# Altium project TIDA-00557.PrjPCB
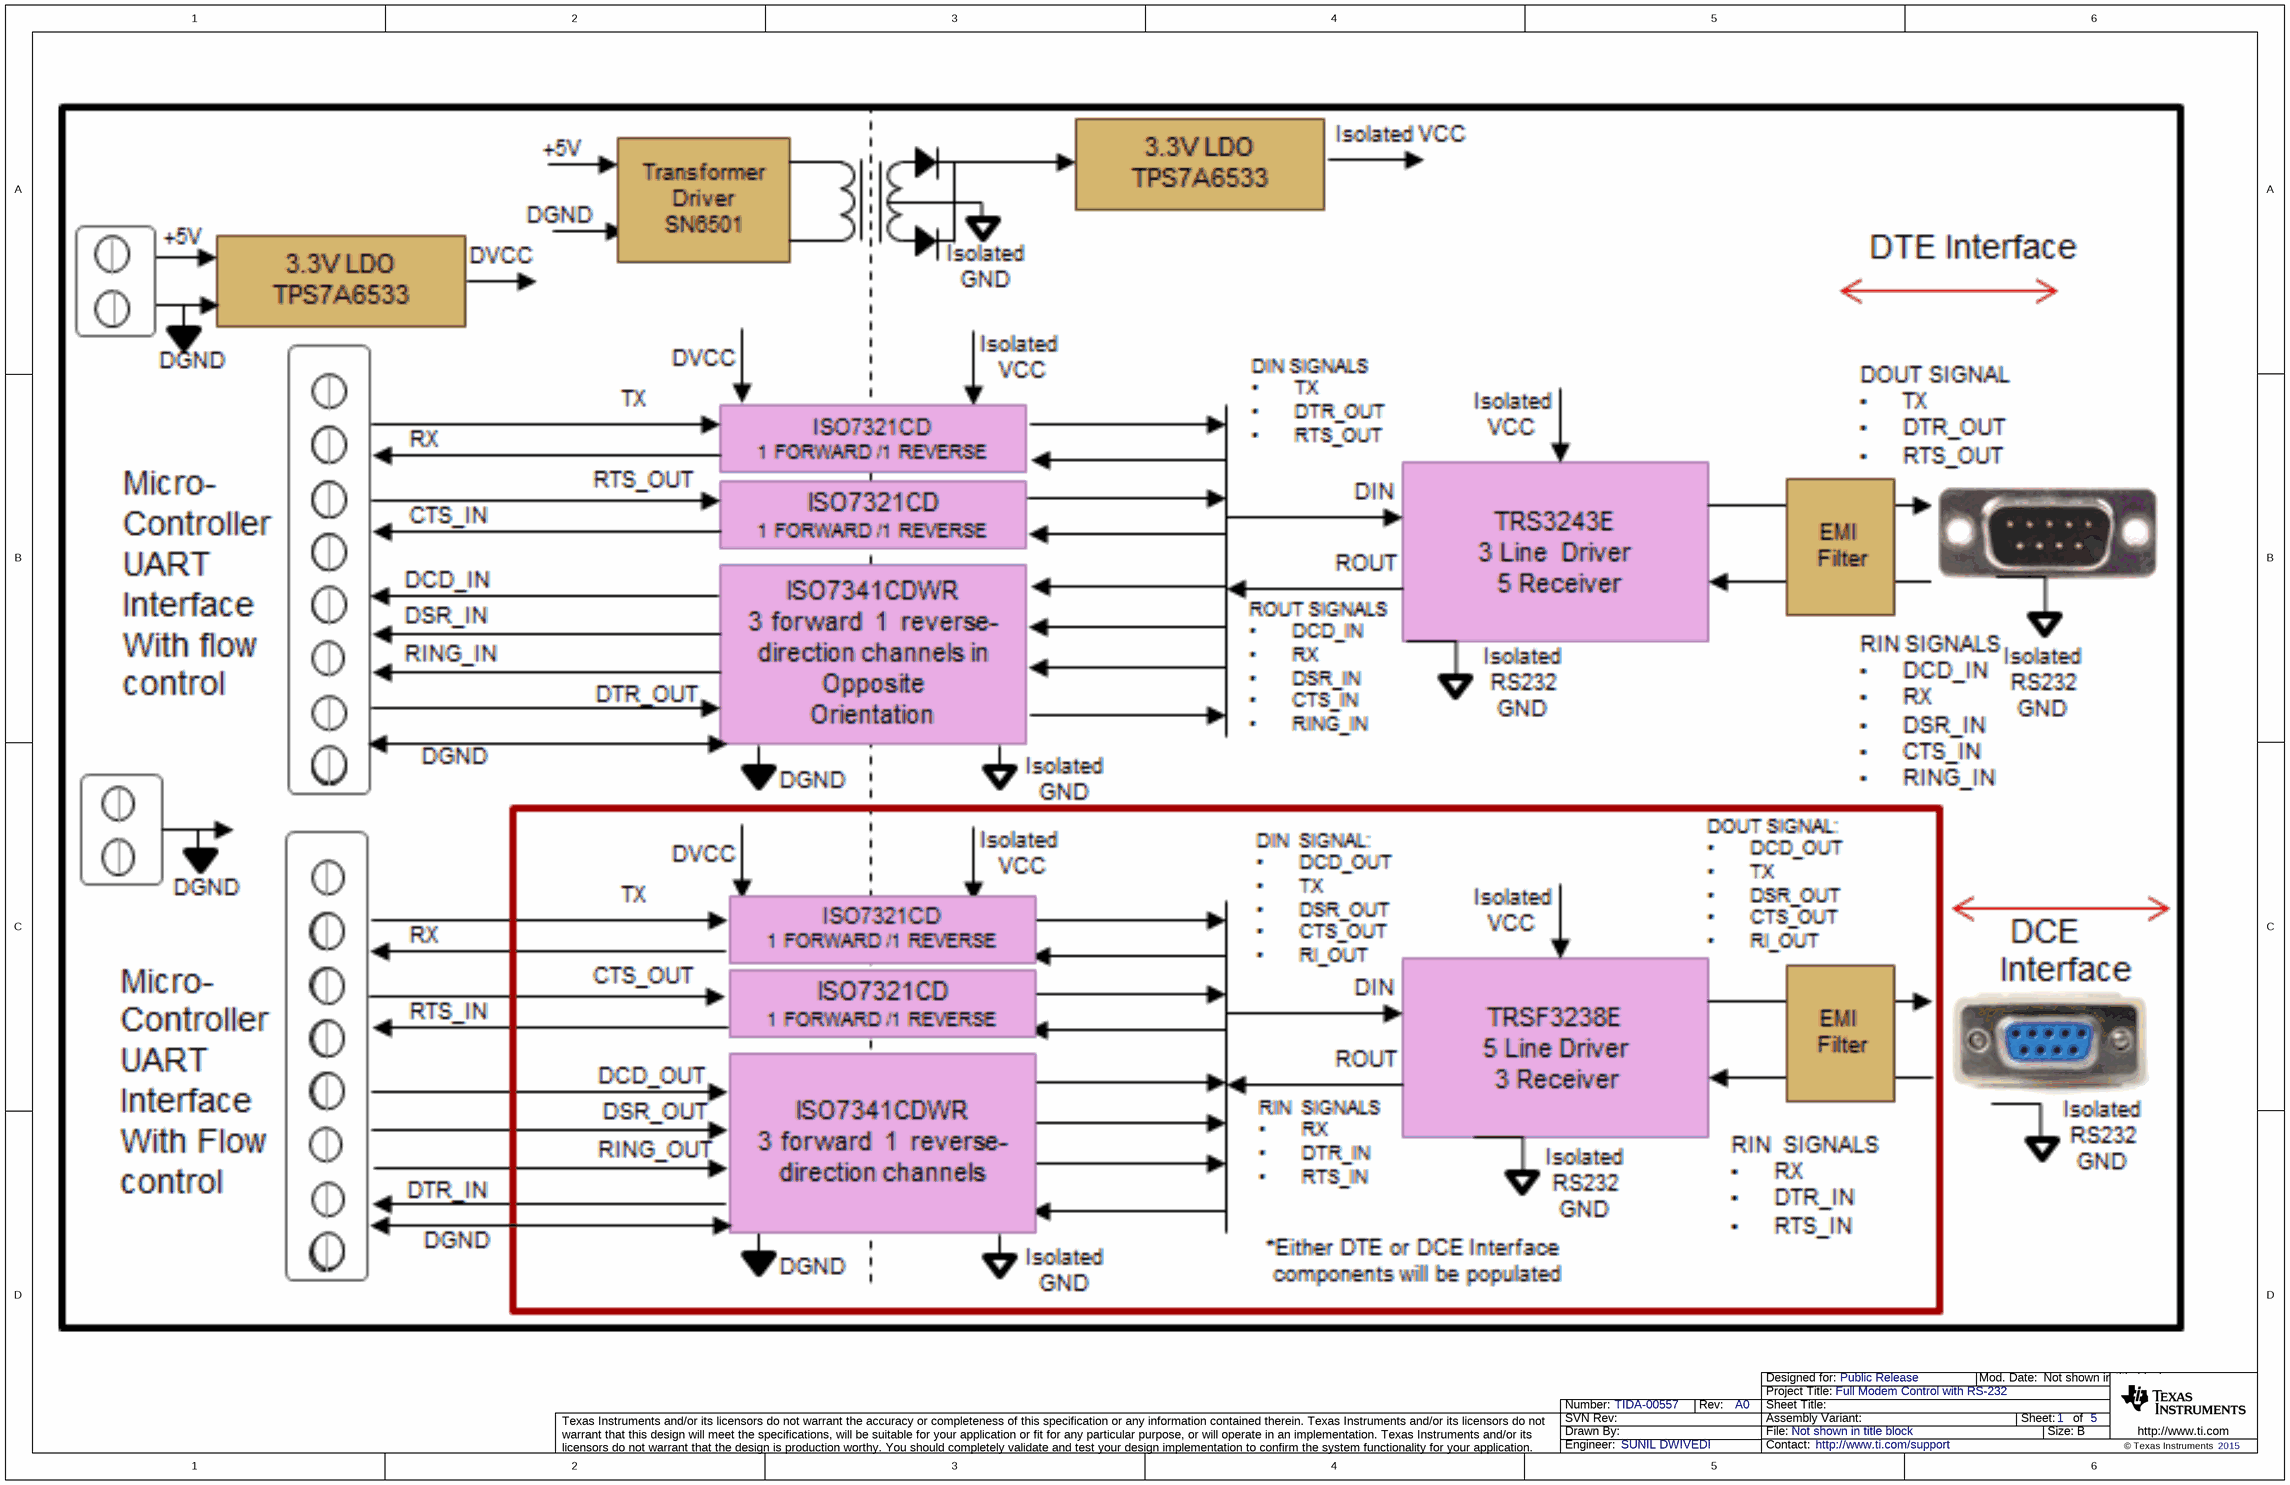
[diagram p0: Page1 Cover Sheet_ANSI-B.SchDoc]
CopyrightYear: 2015; PCB_Layout: AVINASH N; PCB_Rev: E2; PRJ_Customer: Public Release; PRJ_Engineer: SUNIL DWIVEDI; PRJ_Number: TIDA-00557; PRJ_Title: Full Modem Control with RS-232; SCH_Rev: A0; TechSupport: http://www.ti.com/support
5 sheets, 146 parts. Net scope: global (net labels, ports and power ports of the same name join across sheets).
Board file: TIDA-00557.PcbDoc
Sheets:
  Page1 Cover Sheet_ANSI-B.SchDoc
  Page2 DTE-DCE.SchDoc
  Page3 DCE-DTE.SchDoc
  Page4 Power Supply.SchDoc
  Page5 Hardware_ANSI-B.SchDoc

## Sheet Page1 Cover Sheet_ANSI-B.SchDoc
size 431 x 279 mm; Date: Not shown in title block; ApprovedBy: Not shown in title block; CheckedBy: Not shown in title block; Author: Not shown in title block; CompanyName: Not shown in title block; Engineer: Not shown in title block; Organization: Not shown in title block; Address1: Not shown in title block; Address2: Not shown in title block; Address3: Not shown in title block; Address4: Not shown in title block; DocumentNumber: 1; Revision: Use project parameter SCH_Rev; SheetNumber: 1; SheetTotal: 5; PageSetup: Record=PageOptions¦CenterHorizontal=True¦CenterVertical=True¦PrintScale=1.00¦XCorrection=1.00¦YCorrection=1.00¦PrintKind=0¦BorderSize=5000000¦LeftOffset=0¦BottomOffset=0¦Orientation=2¦PaperLength=1000¦PaperWidth=1000¦Scale=100¦PaperSource=15¦PrintQuality=600¦MediaType=1¦DitherType=10¦PaperKind=Letter¦PrintScaleMode=1

## Sheet Page2 DTE-DCE.SchDoc
size 431 x 279 mm; Date: Not shown in title block; ApprovedBy: Not shown in title block; CheckedBy: Not shown in title block; Author: Not shown in title block; CompanyName: Not shown in title block; Engineer: Not shown in title block; Organization: Not shown in title block; Address1: Not shown in title block; Address2: Not shown in title block; Address3: Not shown in title block; Address4: Not shown in title block; DocumentNumber: 1; Revision: Use project parameter SCH_Rev; SheetNumber: 2; SheetTotal: 5; PageSetup: Record=PageOptions¦CenterHorizontal=True¦CenterVertical=True¦PrintScale=1.00¦XCorrection=1.00¦YCorrection=1.00¦PrintKind=0¦BorderSize=5000000¦LeftOffset=0¦BottomOffset=0¦Orientation=2¦PaperLength=1000¦PaperWidth=1000¦Scale=100¦PaperSource=15¦PrintQuality=600¦MediaType=1¦DitherType=10¦PaperKind=Letter¦PrintScaleMode=1
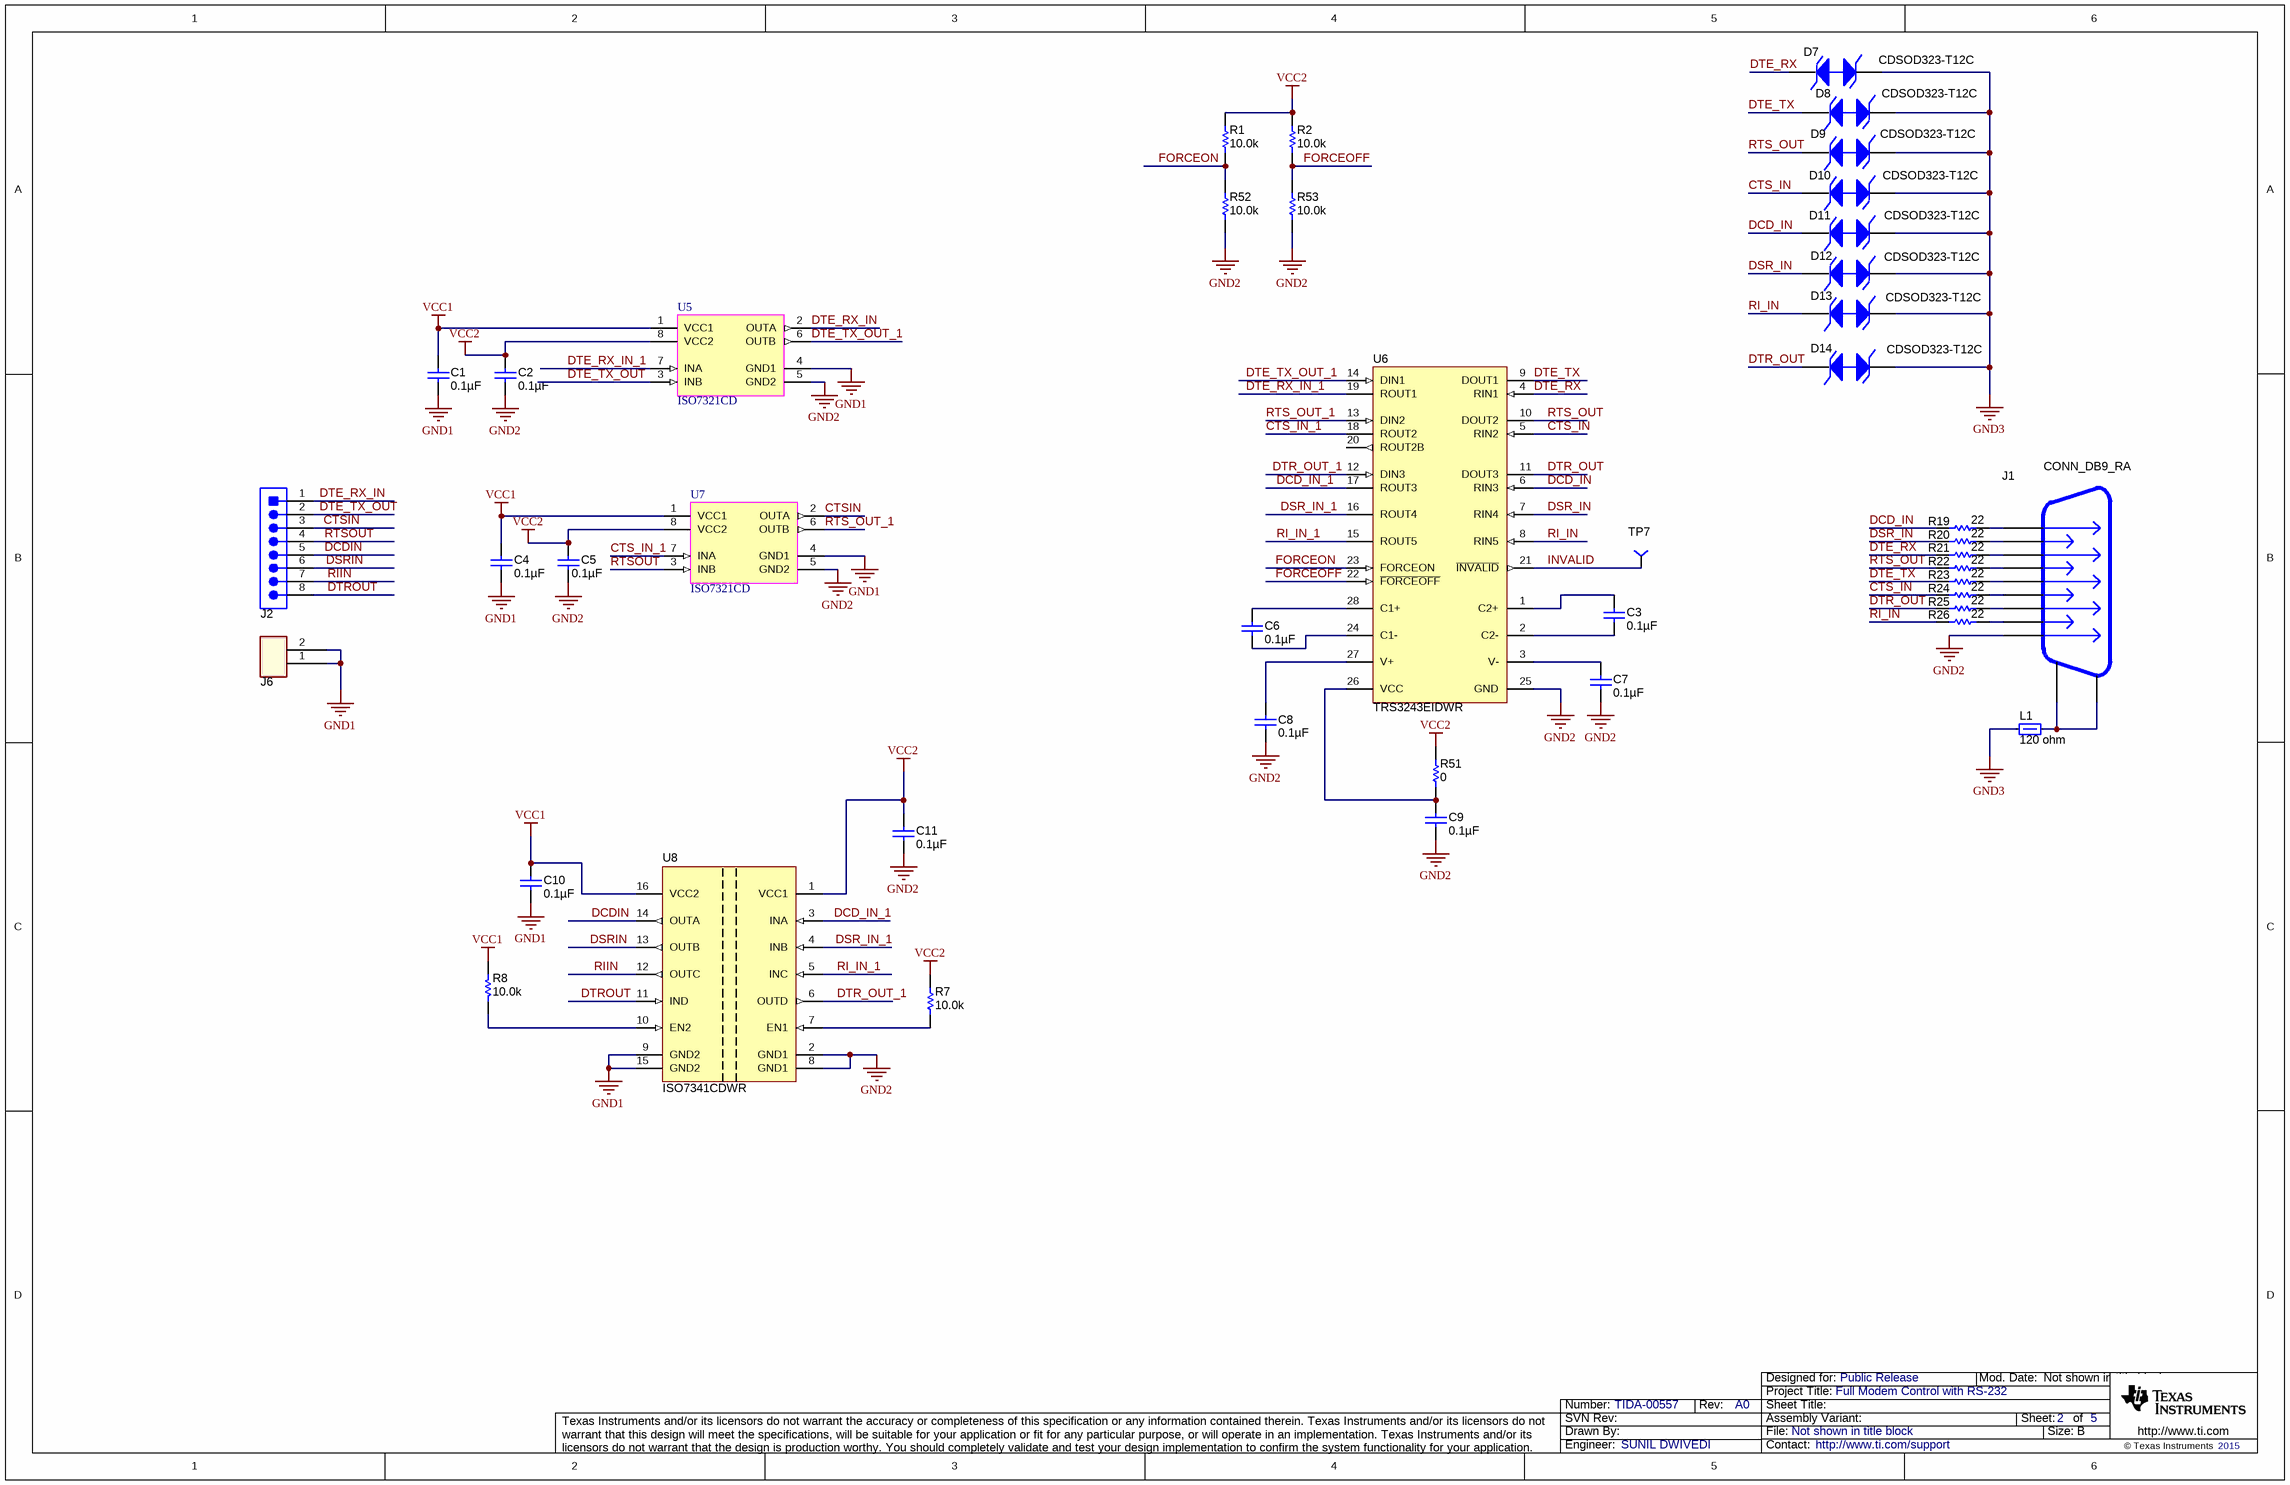
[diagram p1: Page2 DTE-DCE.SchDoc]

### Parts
C1  ValueDisplayed: 0.1µF  [0603]  (hidden comment: C0603C104K5RACTU)
C2  ValueDisplayed: 0.1µF  [0603]  (hidden comment: C0603C104K5RACTU)
C3  ValueDisplayed: 0.1µF  [0603]  (hidden comment: C0603C104K5RACTU)
C4  ValueDisplayed: 0.1µF  [0603]  (hidden comment: C0603C104K5RACTU)
C5  ValueDisplayed: 0.1µF  [0603]  (hidden comment: C0603C104K5RACTU)
C6  ValueDisplayed: 0.1µF  [0603]  (hidden comment: C0603C104K5RACTU)
C7  ValueDisplayed: 0.1µF  [0603]  (hidden comment: C0603C104K5RACTU)
C8  ValueDisplayed: 0.1µF  [0603]  (hidden comment: C0603C104K5RACTU)
C9  ValueDisplayed: 0.1µF  [0603]  (hidden comment: C0603C104K5RACTU)
C10  ValueDisplayed: 0.1µF  [0603]  (hidden comment: C0603C104K5RACTU)
C11  ValueDisplayed: 0.1µF  [0603]  (hidden comment: C0603C104K5RACTU)
D7  CDSOD323-T12C  [sod-323]
D8  CDSOD323-T12C  [sod-323]
D9  CDSOD323-T12C  [sod-323]
D10  CDSOD323-T12C  [sod-323]
D11  CDSOD323-T12C  [sod-323]
D12  CDSOD323-T12C  [sod-323]
D13  CDSOD323-T12C  [sod-323]
D14  CDSOD323-T12C  [sod-323]
J1  CONN_DB9_RA  [DB9_RA]
J2  1725711  [CONN_1725711]  (value not drawn)
J6  CON-OSTVN02A150  [CN2_MTB_P100_PD80_D1.1_S5.54X6.5_STACK]  (value not drawn)
L1  value 120 ohm  [0805_HV]  (hidden comment: BLM21AG121SN1D)
R1  value 10.0k  [0603]  (hidden comment: CRCW060310K0FKEA)
R2  value 10.0k  [0603]  (hidden comment: CRCW060310K0FKEA)
R7  value 10.0k  [0603]  (hidden comment: CRCW060310K0FKEA)
R8  value 10.0k  [0603]  (hidden comment: CRCW060310K0FKEA)
R19  ValueDisplayed: 22  [2512]  (hidden comment: RPC2512JT22R0)
R20  ValueDisplayed: 22  [2512]  (hidden comment: RPC2512JT22R0)
R21  ValueDisplayed: 22  [2512]  (hidden comment: RPC2512JT22R0)
R22  ValueDisplayed: 22  [2512]  (hidden comment: RPC2512JT22R0)
R23  ValueDisplayed: 22  [2512]  (hidden comment: RPC2512JT22R0)
R24  ValueDisplayed: 22  [2512]  (hidden comment: RPC2512JT22R0)
R25  ValueDisplayed: 22  [2512]  (hidden comment: RPC2512JT22R0)
R26  ValueDisplayed: 22  [2512]  (hidden comment: RPC2512JT22R0)
R51  ValueDisplayed: 0  [0603]  (hidden comment: CRCW06030000Z0EA)
R52  value 10.0k  [0603]  (hidden comment: CRCW060310K0FKEA)
R53  value 10.0k  [0603]  (hidden comment: CRCW060310K0FKEA)
TP7  TP-040_RND  [TP-040_RND]  (value not drawn)
U5  ISO7321CD
U6  TRS3243EIDWR  [DW0028A_N]
U7  ISO7321CD
U8  ISO7341CDWR  [DW0016B_HV]

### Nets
GND1: C1.2 C4.2 C10.2 J6.1 J6.2 U5.4(GND1) U7.4(GND1) U8.9(GND2) U8.15(GND2)
GND2: C2.2 C5.2 C7.2 C8.2 C9.2 C11.2 J1.5 R52.2 R53.1 U5.5(GND2) U6.25(GND) U7.5(GND2) U8.2(GND1) U8.8(GND1)
GND3: D7.2 D8.2 D9.2 D10.2 D11.2 D12.2 D13.2 D14.2 L1.2
VCC1: C1.1 C4.1 C10.1 R8.2 U5.1(VCC1) U7.1(VCC1) U8.16(VCC2)
VCC2: C2.1 C5.1 C11.1 R1.2 R2.2 R7.2 R51.1 U5.8(VCC2) U7.8(VCC2) U8.1(VCC1)
CTS_IN: D10.1 R24.1 U6.5(RIN2)
CTS_IN_1: U6.18(ROUT2) U7.7(INA)
CTSIN: J2.3 U7.2(OUTA)
DCD_IN: D11.1 R19.1 U6.6(RIN3)
DCD_IN_1: U6.17(ROUT3) U8.3(INA)
DCDIN: J2.5 U8.14(OUTA)
DSR_IN: D12.1 R20.1 U6.7(RIN4)
DSR_IN_1: U6.16(ROUT4) U8.4(INB)
DSRIN: J2.6 U8.13(OUTB)
DTE_RX: D7.1 R21.1 U6.4(RIN1)
DTE_RX_IN: J2.1 U5.2(OUTA)
DTE_RX_IN_1: U5.7(INA) U6.19(ROUT1)
DTE_TX: D8.1 R23.1 U6.9(DOUT1)
DTE_TX_OUT: J2.2 U5.3(INB)
DTE_TX_OUT_1: U5.6(OUTB) U6.14(DIN1)
DTR_OUT: D14.1 R25.1 U6.11(DOUT3)
DTR_OUT_1: U6.12(DIN3) U8.6(OUTD)
DTROUT: J2.8 U8.11(IND)
FORCEOFF: R2.1 R53.2 U6.22(~{FORCEOFF})
FORCEON: R1.1 R52.1 U6.23(FORCEON)
INVALID: TP7.1 U6.21(~{INVALID})
RI_IN: D13.1 R26.1 U6.8(RIN5)
RI_IN_1: U6.15(ROUT5) U8.5(INC)
RIIN: J2.7 U8.12(OUTC)
RTS_OUT: D9.1 R22.1 U6.10(DOUT2)
RTS_OUT_1: U6.13(DIN2) U7.6(OUTB)
RTSOUT: J2.4 U7.3(INB)
NetC3_1: C3.1 U6.1(C2+)
NetC3_2: C3.2 U6.2(C2-)
NetC6_1: C6.1 U6.28(C1+)
NetC6_2: C6.2 U6.24(C1-)
NetC7_1: C7.1 U6.3(V-)
NetC8_1: C8.1 U6.27(V+)
NetC9_1: C9.1 R51.2 U6.26(VCC)
NetJ1_1: J1.1 R19.2
NetJ1_2: J1.2 R21.2
NetJ1_3: J1.3 R23.2
NetJ1_4: J1.4 R25.2
NetJ1_6: J1.6 R20.2
NetJ1_7: J1.7 R22.2
NetJ1_8: J1.8 R24.2
NetJ1_9: J1.9 R26.2
NetJ1_10: J1.10(MOUNT1) J1.11(MOUNT2) L1.1
NetR7_1: R7.1 U8.7(EN1)
NetR8_1: R8.1 U8.10(EN2)

Not connected (* = marked no-connect by the designer): U6 20(ROUT2B)

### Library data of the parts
C1-C11 = C0603C104K5RACTU: CAP, CERM, 0.1uF, 50V, +/-10%, X7R, 0603; Manufacturer: Kemet; Polarized: N; CompType: Capacitor; U/M: EA; Cap_F: 0.0000001; Tolerance_%: 10; Value1: Unknown; VDC_V: 50; TaMin_C: -55; TaMax_C: 125
D7-D14 = CDSOD323-T15SC: Diode, TVS, ARRAY, 19V, SOD323; Manufacturer: Bourns Inc.; Value: 19
J1 = CONN_DB9_RA: Connector, 9-pin D, Right Angle, Male; Manufacturer: AMP; PartNumber: 747250-4; area: 1.021 inch; Value: 747250-4
J2 = 1725711: Terminal Block, 8x1, 2.54 mm, TH; Manufacturer: Phoenix Contact; SymbolCreator: a0411947; U/M: EA
J6 = CON-OSTVN02A150: CONN TERM BLOCK 2.54MM 2POS PCB; Manufacturer: On Shore Technology Inc; SymbolCreator: x0120606; CompType: Terminal Block
L1 = BLM21AG121SN1D: Ferrite Bead, 120 ohm @ 100 MHz, 0.8 A, 0805; Manufacturer: MuRata; Imax_A: 0.8; DCR_ohm: 0.1; Value1: 0.1 ohm; Value2: 0.8A; ZTyp@100MHz_Ohm: 120
R1 R2 R7 R8 R52 R53 = CRCW060310K0FKEA: RES, 10.0k ohm, 1%, 0.1W, 0603; Manufacturer: Vishay-Dale; CompType: Resistor; Res_ohm: 10000; Value_Code: 10k0; Tolerance_%: 1; Power_W: 0.1; VDC_V: 75; TempCo: 100 ppm/C; EIA_Code: E96; U/M: EA
R19-R26 = CRCW251210R0FKEG: RES SMD 22 OHM 5% 1.5W 2512; Manufacturer: Vishay-Dale; CompType: Resistor; Value: 10.0; Res_ohm: 10; Value_Code: 10R0; Tolerance_%: 1; Value1: 1%; Value2: 1W; VDC_V: 500; TempCo: 100 ppm/C; EIA_Code: E96; U/M: EA
R51 = CRCW06030000Z0EA: RES, 0, 5%, 0.1 W, 0603; Manufacturer: Vishay-Dale; CompType: Resistor; Value: 0; Value_Code: 0000; Tolerance_%: 5; Power_W: 0.1; Value2: 0.1W; VDC_V: 75; TempCo: 200 ppm/C; EIA_Code: E24; U/M: EA
TP7 = TP-040_RND: Test Point, O.040 Hole; Manufacturer: STD; Value: STD
U5 U7 = ISO7321CD: IC, ISOLATOR DGTL 2CH 1/1, SOIC-8, ROHS; Manufacturer: TEXAS INSTRUMENTS; CompType: ISOLATOR IC; SymbolCreator: x0199378
U6 = TRS3243EIDWR: 3-V to 5.5-V Multichannel RS-232 Line Driver / Receiver with ±15-kV IEC ESD Protection, -40 to 85 degC, 28-Pin SOIC (DW), Green (RoHS & no Sb/Br); Manufacturer: Texas Instruments; Alternate Manufacturer: None; Alternate PartNumber: Equivalent; Drivers Per Package: 3; Receivers Per Package: 5; Supply Voltage(s)(V): 3.3 or 5.0; ESD HBM(kV): +/-15; ICC(Max)(mA): 1; Single Supply: TRUE
U8 = ISO7341CDWR: Robust EMC, Low Power, Quad-Channel Digital Isolators, DW0016B; Manufacturer: Texas Instruments; SymbolCreator: Altium; CompType: IC; U/M: EA

## Sheet Page3 DCE-DTE.SchDoc
size 431 x 279 mm; Date: Not shown in title block; ApprovedBy: Not shown in title block; CheckedBy: Not shown in title block; Author: Not shown in title block; CompanyName: Not shown in title block; Engineer: Not shown in title block; Organization: Not shown in title block; Address1: Not shown in title block; Address2: Not shown in title block; Address3: Not shown in title block; Address4: Not shown in title block; DocumentNumber: 1; Revision: Use project parameter SCH_Rev; SheetNumber: 3; SheetTotal: 5; PageSetup: Record=PageOptions|CenterHorizontal=True|CenterVertical=True|PrintScale=1.00|XCorrection=1.00|YCorrection=1.00|PrintKind=0|BorderSize=5000000|LeftOffset=0|BottomOffset=0|Orientation=2|PaperLength=1000|PaperWidth=1000|Scale=100|PaperSource=15|PrintQuality=600|MediaType=1|DitherType=10|PaperKind=Letter|PrintScaleMode=1
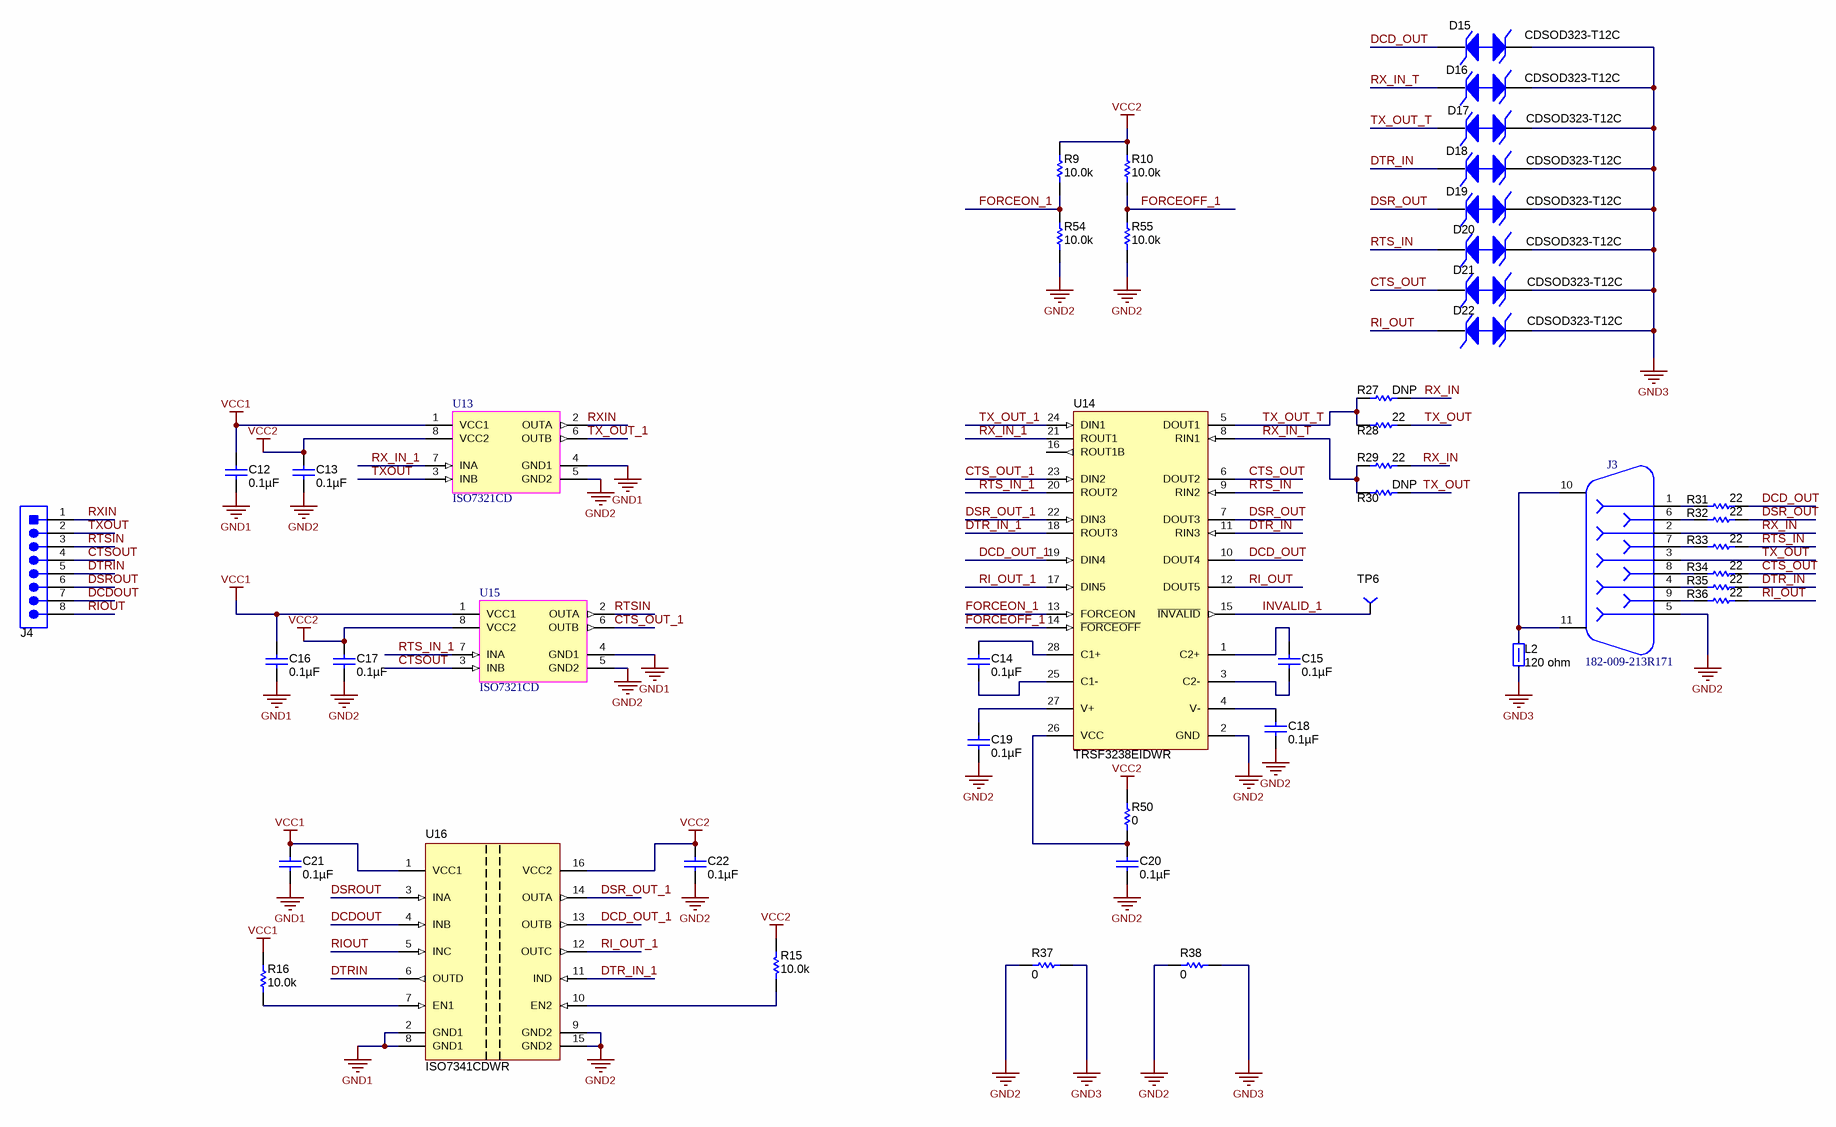
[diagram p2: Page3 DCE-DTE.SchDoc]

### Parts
C12  ValueDisplayed: 0.1µF  [0603]  (hidden comment: C0603C104K5RACTU)
C13  ValueDisplayed: 0.1µF  [0603]  (hidden comment: C0603C104K5RACTU)
C14  ValueDisplayed: 0.1µF  [0603]  (hidden comment: C0603C104K5RACTU)
C15  ValueDisplayed: 0.1µF  [0603]  (hidden comment: C0603C104K5RACTU)
C16  ValueDisplayed: 0.1µF  [0603]  (hidden comment: C0603C104K5RACTU)
C17  ValueDisplayed: 0.1µF  [0603]  (hidden comment: C0603C104K5RACTU)
C18  ValueDisplayed: 0.1µF  [0603]  (hidden comment: C0603C104K5RACTU)
C19  ValueDisplayed: 0.1µF  [0603]  (hidden comment: C0603C104K5RACTU)
C20  ValueDisplayed: 0.1µF  [0603]  (hidden comment: C0603C104K5RACTU)
C21  ValueDisplayed: 0.1µF  [0603]  (hidden comment: C0603C104K5RACTU)
C22  ValueDisplayed: 0.1µF  [0603]  (hidden comment: C0603C104K5RACTU)
D15  CDSOD323-T12C  [sod-323]
D16  CDSOD323-T12C  [sod-323]
D17  CDSOD323-T12C  [sod-323]
D18  CDSOD323-T12C  [sod-323]
D19  CDSOD323-T12C  [sod-323]
D20  CDSOD323-T12C  [sod-323]
D21  CDSOD323-T12C  [sod-323]
D22  CDSOD323-T12C  [sod-323]
J3  182-009-213R171  [NORCOMP_182-009-213R171]
J4  1725711  [CONN_1725711]  (value not drawn)
L2  value 120 ohm  [0805_HV]  (hidden comment: BLM21AG121SN1D)
R9  value 10.0k  [0603]  (hidden comment: CRCW060310K0FKEA)
R10  value 10.0k  [0603]  (hidden comment: CRCW060310K0FKEA)
R15  value 10.0k  [0603]  (hidden comment: CRCW060310K0FKEA)
R16  value 10.0k  [0603]  (hidden comment: CRCW060310K0FKEA)
R27  DNP  [2512]
R28  ValueDisplayed: 22  [2512]  (hidden comment: RPC2512JT22R0)
R29  ValueDisplayed: 22  [2512]  (hidden comment: RPC2512JT22R0)
R30  DNP  [2512]
R31  ValueDisplayed: 22  [2512]  (hidden comment: RPC2512JT22R0)
R32  ValueDisplayed: 22  [2512]  (hidden comment: RPC2512JT22R0)
R33  ValueDisplayed: 22  [2512]  (hidden comment: RPC2512JT22R0)
R34  ValueDisplayed: 22  [2512]  (hidden comment: RPC2512JT22R0)
R35  ValueDisplayed: 22  [2512]  (hidden comment: RPC2512JT22R0)
R36  ValueDisplayed: 22  [2512]  (hidden comment: RPC2512JT22R0)
R37  ValueDisplayed: 0  [0805_HV]  (hidden comment: CRCW08050000Z0EA)
R38  ValueDisplayed: 0  [0805_HV]  (hidden comment: CRCW08050000Z0EA)
R50  ValueDisplayed: 0  [0603]  (hidden comment: CRCW06030000Z0EA)
R54  value 10.0k  [0603]  (hidden comment: CRCW060310K0FKEA)
R55  value 10.0k  [0603]  (hidden comment: CRCW060310K0FKEA)
TP6  TP-040_RND  [TP-040_RND]  (value not drawn)
U13  ISO7321CD
U14  TRSF3238EIDWR  [DW0028A_N]
U15  ISO7321CD
U16  ISO7341CDWR  [DW0016B_HV]

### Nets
GND1: C12.2 C16.2 C21.2 U13.4(GND1) U15.4(GND1) U16.2(GND1) U16.8(GND1)
GND2: C13.2 C17.2 C18.2 C19.2 C20.2 C22.2 J3.5 R37.1 R38.1 R54.1 R55.1 U13.5(GND2) U14.2(GND) U15.5(GND2) U16.9(GND2) U16.15(GND2)
GND3: D15.2 D16.2 D17.2 D18.2 D19.2 D20.2 D21.2 D22.2 L2.2 R37.2 R38.2
VCC1: C12.1 C16.1 C21.1 R16.2 U13.1(VCC1) U15.1(VCC1) U16.1(VCC1)
VCC2: C13.1 C17.1 C22.1 R9.2 R10.2 R15.2 R50.2 U13.8(VCC2) U15.8(VCC2) U16.16(VCC2)
CTS_OUT: D21.1 R34.2 U14.6(DOUT2)
CTS_OUT_1: U14.23(DIN2) U15.6(OUTB)
CTSOUT: J4.4 U15.3(INB)
DCD_OUT: D15.1 R31.2 U14.10(DOUT4)
DCD_OUT_1: U14.19(DIN4) U16.13(OUTB)
DCDOUT: J4.7 U16.4(INB)
DSR_OUT: D19.1 R32.2 U14.7(DOUT3)
DSR_OUT_1: U14.22(DIN3) U16.14(OUTA)
DSROUT: J4.6 U16.3(INA)
DTR_IN: D18.1 R35.2 U14.11(RIN3)
DTR_IN_1: U14.18(ROUT3) U16.11(IND)
DTRIN: J4.5 U16.6(OUTD)
FORCEOFF_1: R10.1 R55.2 U14.14(~{FORCEOFF})
FORCEON_1: R9.1 R54.2 U14.13(FORCEON)
INVALID_1: TP6.1 U14.15(~{INVALID})
RI_OUT: D22.1 R36.2 U14.12(DOUT5)
RI_OUT_1: U14.17(DIN5) U16.12(OUTC)
RIOUT: J4.8 U16.5(INC)
RTS_IN: D20.1 R33.2 U14.9(RIN2)
RTS_IN_1: U14.20(ROUT2) U15.7(INA)
RTSIN: J4.3 U15.2(OUTA)
RX_IN: J3.2 R27.2 R29.2
RX_IN_1: U13.7(INA) U14.21(ROUT1)
RX_IN_T: D16.1 R29.1 R30.1 U14.8(RIN1)
RXIN: J4.1 U13.2(OUTA)
TX_OUT: J3.3 R28.2 R30.2
TX_OUT_1: U13.6(OUTB) U14.24(DIN1)
TX_OUT_T: D17.1 R27.1 R28.1 U14.5(DOUT1)
TXOUT: J4.2 U13.3(INB)
NetC14_1: C14.1 U14.28(C1+)
NetC14_2: C14.2 U14.25(C1-)
NetC15_1: C15.1 U14.1(C2+)
NetC15_2: C15.2 U14.3(C2-)
NetC18_1: C18.1 U14.4(V-)
NetC19_1: C19.1 U14.27(V+)
NetC20_1: C20.1 R50.1 U14.26(VCC)
NetJ3_1: J3.1 R31.1
NetJ3_4: J3.4 R35.1
NetJ3_6: J3.6 R32.1
NetJ3_7: J3.7 R33.1
NetJ3_8: J3.8 R34.1
NetJ3_9: J3.9 R36.1
NetJ3_10: J3.10 J3.11 L2.1
NetR15_1: R15.1 U16.10(EN2)
NetR16_1: R16.1 U16.7(EN1)

Not connected (* = marked no-connect by the designer): U14 16(ROUT1B)

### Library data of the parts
C12-C22 = C0603C104K5RACTU: as C1 on sheet Page2 DTE-DCE
D15-D22 = CDSOD323-T15SC: as D7 on sheet Page2 DTE-DCE
J3 = 182-009-213R171: CONN DB9 FEMALE R/A SOLDER TH; Manufacturer: NorComp; SymbolCreator: a0412235; CompType: Connector; U/M: EA
J4 = 1725711: as J2 on sheet Page2 DTE-DCE
L2 = BLM21AG121SN1D: as L1 on sheet Page2 DTE-DCE
R9 R10 R15 R16 R54 R55 = CRCW060310K0FKEA: as R1 on sheet Page2 DTE-DCE
R27 R30 = CRCW251210R0FKEG: Manufacturer: Vishay-Dale; CompType: Resistor; Value: 10.0; Res_ohm: 10; Value_Code: 10R0; Tolerance_%: 1; Value1: 1%; Value2: 1W; VDC_V: 500; TempCo: 100 ppm/C; EIA_Code: E96; U/M: EA
R28 R29 R31-R36 = CRCW251210R0FKEG: as R19 on sheet Page2 DTE-DCE
R37 R38 = CRCW08050000Z0EA: RES, 0, 5%, 0.125 W, 0805; Manufacturer: Vishay-Dale; CompType: Resistor; Value: 0; Value_Code: 0000; Tolerance_%: 5; Power_W: 0.125; Value2: 0.125W; VDC_V: 150; TempCo: 200 ppm/C; EIA_Code: E24; U/M: EA
R50 = CRCW06030000Z0EA: as R51 on sheet Page2 DTE-DCE
TP6 = TP-040_RND: as TP7 on sheet Page2 DTE-DCE
U13 U15 = ISO7321CD: as U5 on sheet Page2 DTE-DCE
U14 = TRSF3238EIDWR: 3-V to 5.5-V Multichannel RS-232 Line Driver / Receiver with ±15-kV ESD (HBM) Protection, -40 to 85 degC, 28-Pin SOIC (DW),  Green (RoHS & no Sb/Br); Manufacturer: Texas Instruments; Alternate Manufacturer: None; Alternate PartNumber: Equivalent; Drivers Per Package: 5; Receivers Per Package: 3; Supply Voltage(s)(V): 3.3 or 5.0; ESD HBM(kV): +/-15; ICC(Max)(mA): 2; Single Supply: TRUE
U16 = ISO7341CDWR: as U8 on sheet Page2 DTE-DCE

## Sheet Page4 Power Supply.SchDoc
size 431 x 279 mm; Date: Not shown in title block; ApprovedBy: Not shown in title block; CheckedBy: Not shown in title block; Author: Not shown in title block; CompanyName: Not shown in title block; Engineer: Not shown in title block; Organization: Not shown in title block; Address1: Not shown in title block; Address2: Not shown in title block; Address3: Not shown in title block; Address4: Not shown in title block; DocumentNumber: 1; Revision: Use project parameter SCH_Rev; SheetNumber: 4; SheetTotal: 5; PageSetup: Record=PageOptions|CenterHorizontal=True|CenterVertical=True|PrintScale=1.00|XCorrection=1.00|YCorrection=1.00|PrintKind=0|BorderSize=5000000|LeftOffset=0|BottomOffset=0|Orientation=2|PaperLength=1000|PaperWidth=1000|Scale=100|PaperSource=15|PrintQuality=600|MediaType=1|DitherType=10|PaperKind=Letter|PrintScaleMode=1
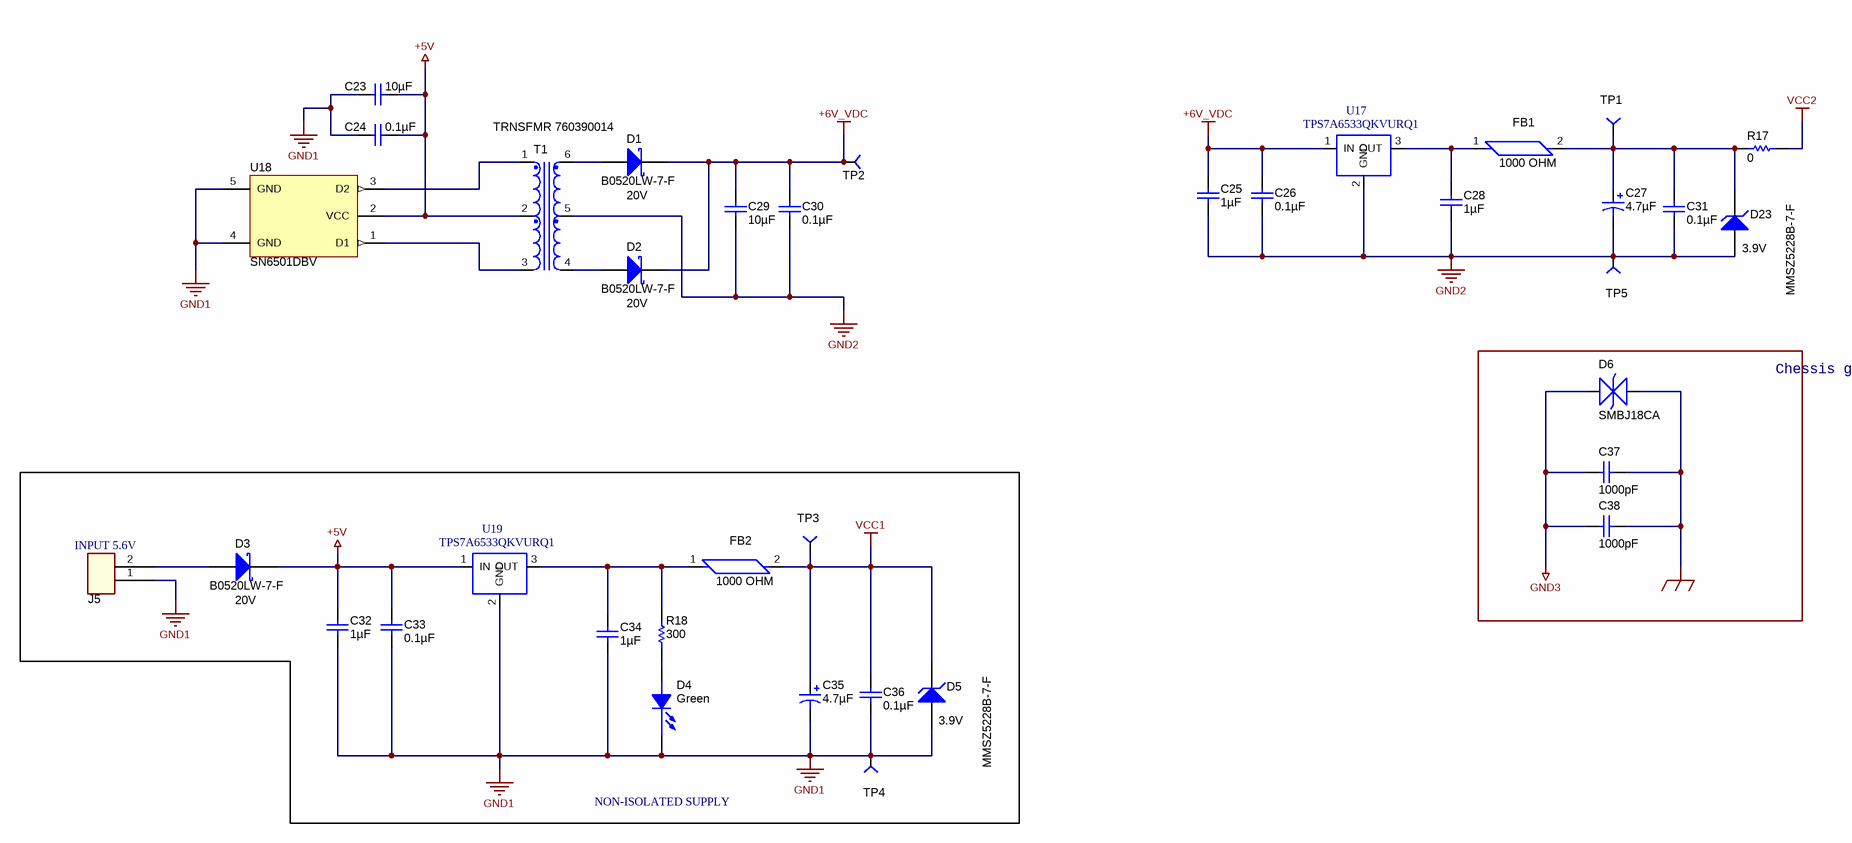
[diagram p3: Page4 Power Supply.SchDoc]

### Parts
C23  ValueDisplayed: 10µF  [1210]
C24  ValueDisplayed: 0.1µF  [0603]
C25  ValueDisplayed: 1µF  [0603]  (hidden comment: C1608X7R1C105K)
C26  ValueDisplayed: 0.1µF  [0603]  (hidden comment: C0603C104K5RACTU)
C27  ValueDisplayed: 4.7µF  [6032-28]  (hidden comment: 293D475X9035C2TE3)
C28  ValueDisplayed: 1µF  [0603]  (hidden comment: C1608X7R1C105K)
C29  ValueDisplayed: 10µF  [1210]
C30  ValueDisplayed: 0.1µF  [0603]
C31  ValueDisplayed: 0.1µF  [0603]  (hidden comment: C0603C104K5RACTU)
C32  ValueDisplayed: 1µF  [0603]  (hidden comment: C1608X7R1C105K)
C33  ValueDisplayed: 0.1µF  [0603]  (hidden comment: C0603C104K5RACTU)
C34  ValueDisplayed: 1µF  [0603]  (hidden comment: C1608X7R1C105K)
C35  ValueDisplayed: 4.7µF  [6032-28]  (hidden comment: 293D475X9035C2TE3)
C36  ValueDisplayed: 0.1µF  [0603]  (hidden comment: C0603C104K5RACTU)
C37  value 1000pF  [1206]  (hidden comment: 202R18W102KV4E)
C38  value 1000pF  [1206]  (hidden comment: 202R18W102KV4E)
D1  B0520LW-7-F  value 20V  [SOD-123]
D2  B0520LW-7-F  value 20V  [SOD-123]
D3  B0520LW-7-F  value 20V  [SOD-123]
D4  value Green  [LED0603AA]  (hidden comment: LED_LG L29K-G2J1-24-Z)
D5  MMSZ5228B-7-F  value 3.9V  [sod-123]
D6  SMBJ18CA  [DIO_SMB_BIAAAA]
D23  MMSZ5228B-7-F  value 3.9V  [sod-123]
FB1  1000 OHM  [0603]
FB2  1000 OHM  [0603]
J5  CON-OSTVN02A150  [CN2_MTB_P100_PD80_D1.1_S5.54X6.5_STACK]  (value not drawn)
R17  value 0  [0603]  (hidden comment: CRCW06030000Z0EA)
R18  value 300  [0603]  (hidden comment: CRCW0603300RJNEA)
T1  TRNSFMR 760390014  [760390015]
TP1  TP-040_RND  [TP-040_RND]  (value not drawn)
TP2  TP-040_RND  [TP-040_RND]  (value not drawn)
TP3  TP-040_RND  [TP-040_RND]  (value not drawn)
TP4  TP-040_RND  [TP-040_RND]  (value not drawn)
TP5  TP-040_RND  [TP-040_RND]  (value not drawn)
U17  TPS7A6533QKVURQ1  [KVU_1]
U18  SN6501DBV  [DBV0005A_N]
U19  TPS7A6533QKVURQ1  [KVU_1]

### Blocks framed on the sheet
Chessis ground: C37 C38 D6

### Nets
+5V: C23.2 C24.2 C32.1 C33.1 D3.1(K) T1.2 U18.2(VCC) U19.1(IN)
+6V_VDC: C25.1 C26.1 C29.1 C30.1 D1.1(K) D2.1(K) TP2.1 U17.1(IN)
GND1: C23.1 C24.1 C32.2 C33.2 C34.2 C35.2(-) C36.2 D4.1(C) D5.2(A) J5.1 TP4.1 U18.4(GND) U18.5(GND) U19.2(GND)
GND2: C25.2 C26.2 C27.2(-) C28.2 C29.2 C30.2 C31.2 D23.2(A) T1.5 TP5.1 U17.2(GND)
GND3: C37.1 C38.1 D6.1
GND_EARTH: C37.2 C38.2 D6.2
VCC1: C35.1(+) C36.1 D5.1(K) FB2.2 TP3.1
VCC2: R17.2
NetC27_1: C27.1(+) C31.1 D23.1(K) FB1.2 R17.1 TP1.1
NetC28_1: C28.1 FB1.1 U17.3(OUT)
NetC34_1: C34.1 FB2.1 R18.2 U19.3(OUT)
NetD1_2: D1.2(A) T1.6
NetD2_2: D2.2(A) T1.4
NetD3_2: D3.2(A) J5.2
NetD4_2: D4.2(A) R18.1
NetT1_1: T1.1 U18.3(D2)
NetT1_3: T1.3 U18.1(D1)

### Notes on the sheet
- (near J5) INPUT 5.6V
- NON-ISOLATED SUPPLY

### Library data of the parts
C23 C29 = GMK325AB7106MM-T: CAP, CERM, 10uF, 35V, +/-20%, X7R, 1210; Manufacturer: Taiyo Yuden; Polarized: N; CompType: Capacitor; U/M: EA; Cap_F: 0.00001; Tolerance_%: 20; Value1: Unknown; VDC_V: 35; TaMin_C: -55; TaMax_C: 125
C24 C26 C30 C31 C33 C36 = C0603C104K5RACTU: as C1 on sheet Page2 DTE-DCE
C25 C28 C32 C34 = C1608X7R1C105K: CAP, CERM, 1uF, 16V, +/-10%, X7R, 0603; Manufacturer: TDK; Polarized: N; CompType: Capacitor; U/M: EA; Cap_F: 0.000001; Tolerance_%: 10; ESR_Ohm: 0.0057; Value1: 0.0057 ohm; VDC_V: 16; TaMin_C: -55; TaMax_C: 125
C27 C35 = 293D475X9035C2TE3: CAP, TA, 4.7uF, 35V, +/-10%, 1.9 ohm, SMD; Manufacturer: Vishay-Sprague; Polarized: Y; CompType: Capacitor; U/M: EA; Cap_F: 0.0000047; Tolerance_%: 10; Value1: 1.9 ohm; VDC_V: 35; ESR_Ohm: 1.9; IRMS_A: 0.24; TaMin_C: -55; TaMax_C: 125; Cap_Case: C
C37 C38 = 202R18W102KV4E: CAP, CERM, 1000pF, 2KV 10% X7R 1206; Manufacturer: Johanson Dielectrics Inc; Polarized: N; CompType: Capacitor; Cap_F: 0.000000001; Tolerance_%: 0
D1-D3 = MBR0520LT1G: Diode, Schottky, 20V, 0.5A, SOD-123; Manufacturer: Diodes Inc; U/M: EA; Vf_V: 0.385; Value2: 0.385V; Io_A: 0.5; Vr_V: 20; TJmax_C: 125; RJC_CperW: 150
D4 = LED_LG L29K-G2J1-24-Z: LED SmartLED Green 570NM; Manufacturer: OSRAM; SymbolCreator: x0120606
D5 D23 = 1SMB5915BT3G: DIODE ZENER 3.9V 500MW SOD123; Manufacturer: Diodes Incorporated; U/M: EA; Power_W: 0.55; Vz_V: 3.9; Value1: 0.55W; RJA_CperW: 226
D6 = SMBJ18CA: TVS 18 VOLT 600 WATT BI-DIR SMB; Manufacturer: Littelfuse Inc
FB1 FB2 = MMZ1608B102C: FERRITE CHIP 1000 OHM 300MA 0603; Manufacturer: TDK Corporation; CompType: Ferrite Bead
J5 = CON-OSTVN02A150: as J6 on sheet Page2 DTE-DCE
R17 = CRCW06030000Z0EA: RES, 0 ohm, 5%, 0.1W, 0603; Manufacturer: Vishay-Dale; CompType: Resistor; Value_Code: 0000; Tolerance_%: 5; Power_W: 0.1; VDC_V: 75; TempCo: 200 ppm/C; EIA_Code: E24; U/M: EA
R18 = CRCW0603300RJNEA: RES, 300 ohm, 5%, 0.1W, 0603; Manufacturer: Vishay-Dale; CompType: Resistor; Value_Code: 300R; Tolerance_%: 5; Power_W: 0.1; VDC_V: 75; TempCo: 200 ppm/C; EIA_Code: E24; U/M: EA
T1 = TRNSFMR 760390015: Transformer 475uH SMD; Manufacturer: Wurth Electronics Midcom
TP1-TP5 = TP-040_RND: as TP7 on sheet Page2 DTE-DCE
U17 U19 = TPS7A6533QKVURQ1: IC, 300-mA 40-V LOW-DROPOUT REGULATOR WITH 25-uA QUIESCENT CURRENT; Manufacturer: TI; Alternate Manufacturer: None; Area: 136210
U18 = SN6501DBV: Transformer Driver for Isolated Power Supplies, DBV0005A; Alternate Manufacturer: None; Manufacturer: Texas Instruments; SymbolCreator: a0411947; CompType: IC; U/M: EA

## Sheet Page5 Hardware_ANSI-B.SchDoc
size 431 x 279 mm; Date: Not shown in title block; ApprovedBy: Not shown in title block; CheckedBy: Not shown in title block; Author: Not shown in title block; CompanyName: Not shown in title block; Engineer: Not shown in title block; Organization: Not shown in title block; Address1: Not shown in title block; Address2: Not shown in title block; Address3: Not shown in title block; Address4: Not shown in title block; DocumentNumber: 1; Revision: Use project parameter SCH_Rev; SheetNumber: 5; SheetTotal: 5; PageSetup: Record=PageOptions|CenterHorizontal=True|CenterVertical=True|PrintScale=1.00|XCorrection=1.00|YCorrection=1.00|PrintKind=0|BorderSize=5000000|LeftOffset=0|BottomOffset=0|Orientation=2|PaperLength=1000|PaperWidth=1000|Scale=100|PaperSource=15|PrintQuality=600|MediaType=1|DitherType=10|PaperKind=Letter|PrintScaleMode=1
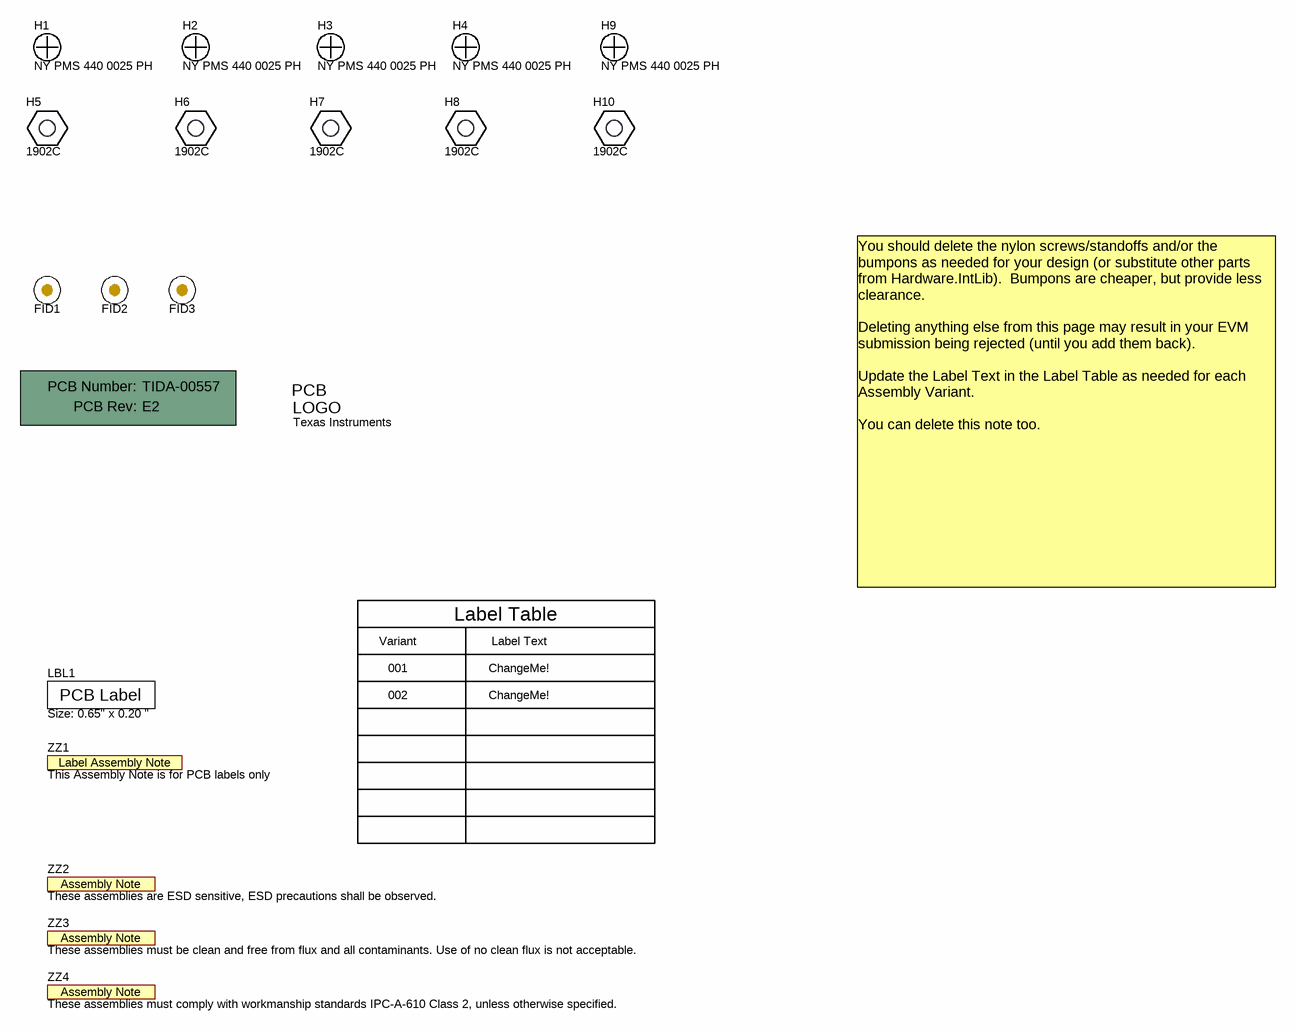
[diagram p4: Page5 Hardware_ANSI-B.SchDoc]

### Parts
!PCB1  Printed Circuit Board  (value not drawn)  (mechanical)
FID1  Fiducial  [Fiducial10-20]  (value not drawn)
FID2  Fiducial  [Fiducial10-20]  (value not drawn)
FID3  Fiducial  [Fiducial10-20]  (value not drawn)
H1  NY PMS 440 0025 PH  [NY PMS 440 0025 PH]
H2  NY PMS 440 0025 PH  [NY PMS 440 0025 PH]
H3  NY PMS 440 0025 PH  [NY PMS 440 0025 PH]
H4  NY PMS 440 0025 PH  [NY PMS 440 0025 PH]
H5  1902C  [Keystone_1902C]
H6  1902C  [Keystone_1902C]
H7  1902C  [Keystone_1902C]
H8  1902C  [Keystone_1902C]
H9  NY PMS 440 0025 PH  [NY PMS 440 0025 PH]
H10  1902C  [Keystone_1902C]
LBL1  Size: 0.65" x 0.20 "  [Label_650x200]
Logo1  Texas Instruments  [TI_Stacked_Overlay_Small]  (no BOM)
ZZ1  This Assembly Note is for PCB labels only  [AssemblyNoteLabel]  (no BOM)
ZZ2  These assemblies are ESD sensitive, ESD precautions shall be observed.  [AssemblyNote]  (no BOM)
ZZ3  These assemblies must be clean and free from flux and all contaminants. Use of no clean flux is not acceptable.  [AssemblyNote]  (no BOM)
ZZ4  These assemblies must comply with workmanship standards IPC-A-610 Class 2, unless otherwise specified.  [AssemblyNote]  (no BOM)

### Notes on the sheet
- Variant
- Label Table
- Label Text
- You should delete the nylon screws/standoffs and/or the bumpons as needed for your design (or substitute other parts from Hardware.IntLib).  Bumpons are cheaper, but provide less clearance.
  Deleting anything else from this page may result in your EVM submission being rejected (until you add them back).
  Update the Label Text in the Label Table as needed for each Assembly Variant.
  You can delete this note too.
- 001
- 002
- ChangeMe!

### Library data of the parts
!PCB1 = PCB: Manufacturer: Any; PartNumber: TIDA-00557; SymbolCreator: a0412235
FID1-FID3 = Fiducial: Fiducial mark.  There is nothing to buy or mount.; SymbolCreator: codlsc
H1-H4 H9 = NY PMS 440 0025 PH: Machine Screw, Round, #4-40 x 1/4, Nylon, Philips panhead; Manufacturer: B&F Fastener Supply; CompType: Hardware; SymbolCreator: codlsc; U/M: EA
H5-H8 H10 = 1902C: Standoff, Hex, 0.5"L #4-40 Nylon; Manufacturer: Keystone; CompType: Hardware
LBL1 = THT-14-423-10: Thermal Transfer Printable Labels, 0.650" W x 0.200" H - 10,000 per roll; Manufacturer: Brady; SymbolCreator: a0412235; CompType: Label
Logo1 = TI_Logo: Texas Instrument Corporate Signature; SymbolCreator: codlsc
ZZ1 = AssemblyNoteLabel: SymbolCreator: a0412235
ZZ2-ZZ4 = AssemblyNote: SymbolCreator: codlsc

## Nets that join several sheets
GND1: Page2 DTE-DCE (9 pins), Page3 DCE-DTE (7 pins), Page4 Power Supply (14 pins)
GND2: Page2 DTE-DCE (14 pins), Page3 DCE-DTE (16 pins), Page4 Power Supply (11 pins)
GND3: Page2 DTE-DCE (9 pins), Page3 DCE-DTE (11 pins), Page4 Power Supply (C37.1 C38.1 D6.1)
VCC1: Page2 DTE-DCE (7 pins), Page3 DCE-DTE (7 pins), Page4 Power Supply (5 pins)
VCC2: Page2 DTE-DCE (10 pins), Page3 DCE-DTE (10 pins), Page4 Power Supply (R17.2)

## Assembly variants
001: not fitted FID1 FID2 FID3 R27 R30 R52 R53 R54 R55 U13 U14 U15 U16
